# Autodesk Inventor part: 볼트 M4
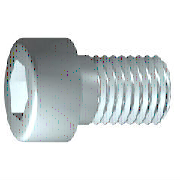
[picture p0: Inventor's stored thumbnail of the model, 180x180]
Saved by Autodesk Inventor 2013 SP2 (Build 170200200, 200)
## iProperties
IsCustomPart: 1
Created: 2012-02
Part Number: 볼트 M4
Material: 강철, 연강
Description: 6각머리 태핑 나사
Document SubType Name: Modeling
Standard: KS B 1003
Designer: mduedu
Standards Organization: KS
Language: ko-KR
Size Designation: M 4 x 10
Categories: <MemberInstance><Categories><Category DisplayName="조임쇠" InternalName="e4da775c-781d-43d5-af7c-5136215cf5a6" Mnemonic="FSTN"><Category DisplayName="볼트" InternalN
Density: 7.86 g/cm^3
Mass: 2.0371 g
Surface Area: 3.0572 cm^2
Volume: 0.259174 cm^3
Author: mduedu
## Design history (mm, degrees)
sketch "스케치1"
  geometry: L1 (-1, 0)-(10, 0); L2 (10, 0)-(10, 2); L3 (10, 2)-(1.75, 2); L4 (1.75, 2)-(1.32, 2); L5 (1.32, 2)-(0, 2); L6 (0, 2)-(0, 3.5); L7 (0, 3.5)-(-4, 3.5); L8 (-4, 3.5)-(-4, 1.732); L9 (-4, 1.732)-(-2, 1.732); L10 (-2, 1.732)-(-1, 0); L11 (-6.8, 0)-(12.8, 0) reference; L12 (0, -0.7)-(0, 4.2) reference; L13 (1.75, 2)-(0, 2)
  constraints: 22 end point, 6 parallel, 2 collinear, 2 perpendicular, 1 horizontal, 1 point on line
  dimensions: "d1" = 8.25 distance from line of L3.end L2 (= GEL); "d2" = 0.42952 distance of L4.end L3.end (computed from GAL); "d3" = 4 distance between parallel lines of L8 L6 (= KOH); "d4" = 2 distance of L8.end L9.end (= INTI); "d5" = 60 deg angle of L10 L1; "d6" = 4 diameter of L3 L1 (= GD); "d7" = 4 diameter of L5 L1 (= BDM); "d8" = 3.4641 diameter of L9 L1 (= 1.1547 x SW); "d9" = 7 diameter of L7 L1 (= KOD); "d26" = 10 distance between parallel lines of L12 L2 (= NLG)
revolve "본체" sketch "스케치1" stored, may be unused: angle "d10" = 90 deg
sketch "스케치2"
  geometry: L1 (0, -4.9)-(0, 4.9) reference; L2 (-4.9, 0)-(4.9, 0) reference; L3 (1.732, 0)-(0.866, -1.5); L4 (0.866, -1.5)-(-0.866, -1.5); L5 (-0.866, -1.5)-(-1.732, 0); L6 (-1.732, 0)-(-0.866, 1.5); L7 (-0.866, 1.5)-(0.866, 1.5); L8 (0.866, 1.5)-(1.732, 0); 2 further points
  constraints: 12 end point, 1 coincident, 1 horizontal alignment, 1 point on line, 12 other
extrude "슬롯" join sketch "스케치2" stored distance "d11" = 10; taper "d12" = 0 deg
workplane "Work Plane1"
fillet "Fillet2" dims "d30" = 0.1 (= R)
body "Solid1"
fillet "모깎기1" dims "d17" = 0.4 (= RR)
feature "스레드" dims "d13" = 8.25 (= GEL), "d14" = 0
chamfer "모따기1" distance "d15" = 0.42941 (= -0.5 x SPD + 0.5 x GD); stored, may be unused: second distance "d16" = 0.42941 (= GUL), angle "d27" = 45 deg
other parameters: "GD" = 4 (= NND) [user parameter; used in 2 equation terms], "NLG" = 10 [user parameter; used in 1 equation term], "GEL" = 8.25 [user parameter; used in 2 equation terms], "KOD" = 7 [user parameter; used in 1 equation term], "KOH" = 4 [user parameter; used in 1 equation term], "INTI" = 2 [user parameter; used in 1 equation term], "GAL" = 0.42941 (= 0.61345 x PTC) [user parameter; used in 1 equation term], "GUL" = 0.42941 (= 0.61345 x PTC) [user parameter; used in 1 equation term], "BDM" = 4 (= NND) [user parameter; used in 1 equation term], "SW" = 3 [user parameter; used in 2 equation terms], "RR" = 0.4 [user parameter; used in 1 equation term], "SPD" = 3.14117 (= NND - 1.2269 x PTC) [user parameter; used in 1 equation term], "d19" = 0, "d28" = 0, "d29" = 0, "R" = 0.1 [user parameter; used in 1 equation term], "PHH" = 0.2 [user parameter], "GD1" = 3.14117 (= THREADDIA - 1.2269 x PTC) [user parameter], "THREADDIA" = 4 [user parameter; used in 1 equation term], "FAWI" = 45 deg [user parameter], "TPU" = 14.28571 (computed from PTC) [user parameter], "PTC" = 0.7 [user parameter; used in 5 equation terms], "NND" = 4 [user parameter; used in 3 equation terms], "TOA" = 30 deg [user parameter], "E0" = 3.465 (= 1.155 x SW) [user parameter]
